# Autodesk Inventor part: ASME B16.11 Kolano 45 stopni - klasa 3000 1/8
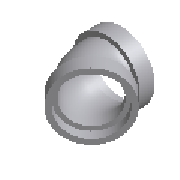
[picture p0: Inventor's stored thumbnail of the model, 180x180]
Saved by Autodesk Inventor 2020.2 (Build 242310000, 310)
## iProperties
Manager: www.cadconsulting.pl
Company: Fabian Stasiak CAD Consulting
Created: 2014-02
Part Number: ASME B16.11 Kolano 45 stopni - klasa 3000 1/8
Material: Stal
Description: Kolano 45º, kute, do przyspawania - klasa 3000
Document SubType Name: Modeling
Standard: ASME B16.11
Designer: F.Stasiak
Standard Revision: 2005
Standards Organization: ANSI
Language: pl-PL
Size Designation: 1/8
Categories: <MemberInstance><Categories><Category DisplayName="Rury cienko- i grubościenne" InternalName="4347fa0f-2144-441d-94cd-e3e15c92b736" Mnemonic="TUBEANDPIPE"><Cate
Density: 1 g/cm^3
Appearance: Płyta
Catalog Web Link: www.expertbooks.pl
NAME: PIPING: ASME B16.11 45 Deg Elbow - Class 3000
DATA: <meta><inlinegroups number="0" deflen="0"></inlinegroups><connections number="2"></connections><angles><a>2.35619449019235</a></angles></meta>
IsCustomPart: 0
Author: F.Stasiak
Subject: Zbiór ćwiczeń. Autodesk Inventor 2020. Kurs Professional
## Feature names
1. Revolve1
2. Sweep1
3. Revolve2
## Parameters: B = 10.668 mm, D = 6.0706 mm, C1 = 3.175 mm, G = 2.413 mm, J1 = 9.652 mm, A = 7.874 mm, d0 = 6.0706 mm, d1 = 10.668 mm, d2 = 3.175 mm, d3 = 3.175 mm, d4 = 9.652 mm, d5 = 2.413 mm, d6 = 0.762 mm, d8 = 90 deg, d7 = 45 deg, d9 = 3.937 mm, d10 = 3.937 mm, d11 = 5.4483 mm, d12 = 6.0706 mm, d13 = 10.8966 mm, d14 = 0, d15 = 6.0706 mm, d16 = 10.668 mm, d17 = 3.175 mm, d18 = 0.762 mm, d19 = 3.175 mm, d20 = 9.652 mm, d21 = 2.413 mm, d25 = 90 deg, d26 = 0, Size_Designation = 1.25 mm
